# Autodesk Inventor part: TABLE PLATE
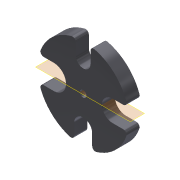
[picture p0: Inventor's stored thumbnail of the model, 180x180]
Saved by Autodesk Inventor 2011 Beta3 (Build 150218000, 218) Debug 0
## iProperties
Shininess: 64.0
Length Units: 11272
Angle Units: 11279
Time Units: 11290
Mass Units: 11286
Length Display Precision: 3
Angle Display Precision: 2
Compacted: True
Part Number: TABLE PLATE
Document SubType Name: Modeling
Created: 2003-11
Designer: Autodesk, Inc.
Manufacturer: Standard
Standards Organization: Custom
Mass: 435.491 g
Surface Area: 143.439 cm^2
Volume: 55.5473 cm^3
Density: 7.84 g/cm^3
Material: Steel, High Strength Low Alloy
Density: 0.0
Volumn: 0.0
Area: 0.0
PropertySet Name: Model Information
Control State: 0
Master: False
Checked Out: False
Author: Autodesk, Inc.
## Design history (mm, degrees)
sketch "Sketch1"
  geometry: C1 r 44.45 at (0, 0); 1 further point
  constraints: 1 centre point, 1 coincident
  dimensions: "d0" = 88.9 diameter of C1
extrude "Extrusion1" new body sketch "Sketch1" distance "d1" = 12.7; taper "d2" = 0 deg
sketch "Sketch2"
  geometry: L1 (-7.137, 43.873)-(-7.137, 28.575); L2 (7.137, 43.873)-(7.137, 28.575); L3 (0, 0)-(0, 40.794); L4 (0, 0)-(-21.298, 0); L5 (-8.725, -28.575)-(-8.725, -43.585); L6 (8.725, -28.575)-(8.725, -43.585); L7 (-28.575, 11.9)-(-42.828, 11.9); L8 (-28.575, -11.9)-(-42.828, -11.9); L9 (28.575, 10.312)-(43.237, 10.312); L10 (28.575, -10.312)-(43.237, -10.312); A1 r 7.137 centre (0, 28.575) between (-7.137, 28.575) and (7.137, 28.575); A2 r 8.725 centre (0, -28.575) between (8.725, -28.575) and (-8.725, -28.575); A3 r 11.9 centre (-28.575, 0) between (-28.575, -11.9) and (-28.575, 11.9); A4 r 10.312 centre (28.575, 0) between (28.575, 10.312) and (28.575, -10.312); A5 r 28.575 centre (0, 0) between (0, 28.575) and (28.575, 0)
  constraints: 20 end point, 11 point on circle, 8 tangent, 5 centre point, 4 horizontal, 4 point on line, 3 parallel, 2 perpendicular, 1 coincident, 1 vertical, 9 other
  dimensions: "d3" = 14.2748 diameter of A1; "d4" = 28.575 distance of L3.start A1.centre; "d7" = 8.7249 radius of A2; "d8" = 28.575 distance of L3.start A2.centre; "d9" = 23.7998 diameter of A3; "d10" = 20.6248 diameter of A4
extrude "Extrusion2" cut sketch "Sketch2" stored distance "d5" = 12.7; taper "d6" = 0 deg
fillet "Fillet1" dims "d11" = 3.175
sketch "Sketch3"
  geometry: C1 r 3.175 at (0, 0); 1 further point
  constraints: 1 centre point, 1 coincident
  dimensions: "d12" = 6.35 diameter of C1
extrude "Extrusion3" cut sketch "Sketch3" stored distance "d13" = 12.7; taper "d14" = 0 deg
body "Solid1"
